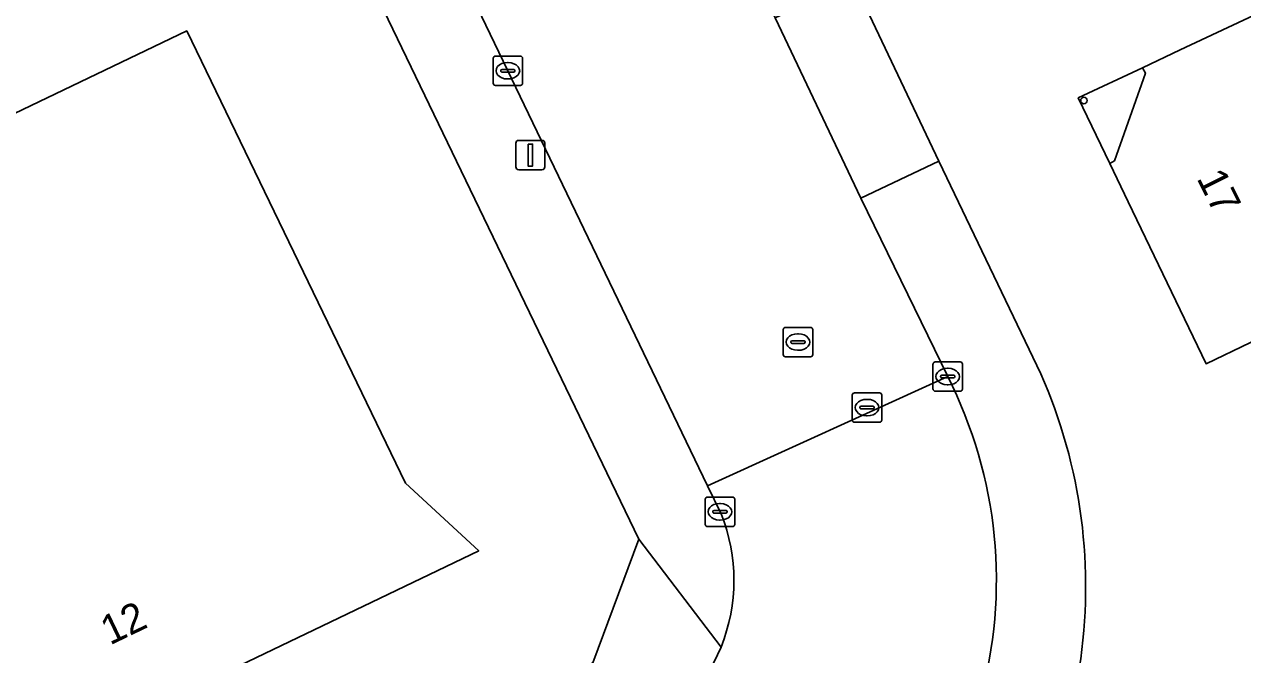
# Model space of a CAD drawing. Extents: x 157692 to 159674, y 381452 to 383291.
# Drawn here: x 158101.97 to 158143.43, y 381697.38 to 381718.82 of the extents above; entities that cross this region are included whole.
import ezdxf

# ---------------------------------------------------------------- set-up
doc = ezdxf.new("R2010")
doc.units = 0
for name, color, linetype in [('IMGEO_Erf', 7, 'Continuous'), ('IMGEO_Kolk', 7, 'Continuous'), ('IMGEO_Lichtmast', 7, 'Continuous'), ('IMGEO_Pand', 7, 'Continuous'), ('IMGEO_Pand_nummerreeks', 7, 'Continuous'), ('IMGEO_Pand_overbouw', 7, 'Continuous'), ('IMGEO_Rijbaan_lokaal_gesloten', 7, 'Continuous'), ('IMGEO_Rioolput', 7, 'Continuous'), ('IMGEO_Voetpad_open', 7, 'Continuous')]:
    doc.layers.add(name, color=color, linetype=linetype)

msp = doc.modelspace()

# ---------------------------------------------------------------- linework, layer by layer
at = {"layer": 'IMGEO_Erf'}
for points in [[(158092.487, 381798.744), (158092.916, 381798.939), (158095.512, 381792.931), (158095.193, 381792.79), (158096.925, 381789.189), (158099.538, 381783.755), (158104.632, 381773.16), (158105.509, 381771.337), (158108.516, 381765.1), (158109.23, 381763.603), (158112.225, 381757.328), (158115.269, 381751.09), (158115.795, 381750), (158119.248, 381742.84), (158125.511, 381729.855), (158128.564, 381723.514), (158130.19, 381720.284), (158133.095, 381714.162), (158136.569, 381706.935)], [(158006.881, 381609.083), (158005.905, 381627.867), (158005.466, 381636.382), (158005.223, 381641.106), (158032.78, 381654.365), (158038.282, 381657.004), (158060.573, 381667.757), (158067.21, 381670.951), (158069.612, 381672.132), (158075.377, 381674.875), (158095.213, 381684.451), (158107.373, 381690.341), (158121.318, 381697.1), (158122.884, 381701.311), (158109.399, 381729.267), (158106.88, 381734.578), (158102.545, 381743.606), (158102.331, 381744.049), (158099.751, 381749.471), (158099.496, 381750), (158086.302, 381777.417), (158083.311, 381783.632), (158080.659, 381789.142)]]:
    msp.add_lwpolyline(points, dxfattribs=at)
for points in [[(158151.951, 381730.299), (158166.876, 381737.497), (158174.051, 381722.618), (158146.716, 381709.452), (158142.191, 381707.273), (158139.542, 381712.78), (158138.914, 381714.086), (158139.078, 381714.178), (158140.124, 381717.153), (158140.027, 381717.345), (158141.314, 381717.95), (158150.29, 381722.166), (158147.447, 381728.127)], [(158107.496, 381718.594), (158114.941, 381703.211), (158117.435, 381700.917), (158095.837, 381690.555), (158087.076, 381708.818)]]:
    msp.add_lwpolyline(points, close=True, dxfattribs=at)
for centre, radius, start, end in [((158138.034, 381716.229), 0.11, 0, 180), ((158138.034, 381716.229), 0.11, 180, 0), ((158120.126, 381699.695), 17.966, 351.1206, 23.7643)]:
    msp.add_arc(centre, radius, start, end, dxfattribs=at)
at = {"layer": 'IMGEO_Kolk'}
for p, q in [((158118.001, 381717.74), (158118.853, 381717.74)), ((158117.926, 381716.814), (158117.926, 381717.666)), ((158118.414, 381717.52), (158118.439, 381717.52)), ((158118.927, 381717.666), (158118.927, 381716.814)), ((158118.185, 381717.234), (158118.185, 381717.246)), ((158118.623, 381717.197), (158118.225, 381717.197)), ((158118.228, 381717.283), (158118.626, 381717.283)), ((158118.437, 381716.96), (158118.412, 381716.96)), ((158118.669, 381717.246), (158118.669, 381717.234)), ((158118.853, 381716.74), (158118.001, 381716.74)), ((158132.971, 381707.34), (158133.823, 381707.34)), ((158132.896, 381706.414), (158132.896, 381707.266)), ((158133.384, 381707.12), (158133.409, 381707.12)), ((158133.897, 381707.266), (158133.897, 381706.414)), ((158133.155, 381706.834), (158133.155, 381706.846)), ((158133.593, 381706.797), (158133.195, 381706.797)), ((158133.198, 381706.883), (158133.596, 381706.883)), ((158133.407, 381706.56), (158133.382, 381706.56)), ((158133.639, 381706.846), (158133.639, 381706.834)), ((158133.823, 381706.34), (158132.971, 381706.34)), ((158125.146, 381701.813), (158125.146, 381702.665)), ((158125.221, 381702.739), (158126.073, 381702.739)), ((158125.634, 381702.519), (158125.659, 381702.519)), ((158126.147, 381702.665), (158126.147, 381701.813)), ((158125.405, 381702.233), (158125.405, 381702.245)), ((158125.843, 381702.196), (158125.445, 381702.196)), ((158125.448, 381702.282), (158125.846, 381702.282)), ((158125.657, 381701.959), (158125.632, 381701.959)), ((158125.889, 381702.245), (158125.889, 381702.233)), ((158126.073, 381701.739), (158125.221, 381701.739))]:
    msp.add_line(p, q, dxfattribs=at)
for points in [[(158118.001, 381717.74), (158118.853, 381717.74)], [(158117.926, 381716.814), (158117.926, 381717.666)], [(158118.927, 381717.666), (158118.927, 381716.814)], [(158118.853, 381716.74), (158118.001, 381716.74)], [(158132.971, 381707.34), (158133.823, 381707.34)], [(158132.896, 381706.414), (158132.896, 381707.266)], [(158133.897, 381707.266), (158133.897, 381706.414)], [(158133.823, 381706.34), (158132.971, 381706.34)], [(158125.146, 381701.813), (158125.146, 381702.665)], [(158125.221, 381702.739), (158126.073, 381702.739)], [(158126.147, 381702.665), (158126.147, 381701.813)], [(158126.073, 381701.739), (158125.221, 381701.739)]]:
    msp.add_lwpolyline(points, dxfattribs=at)
for centre, radius, start, end in [((158118.003, 381717.664), 0.0765, 91.552, 178.448), ((158118.003, 381717.664), 0.0765, 91.552, 178.448), ((158118.851, 381717.664), 0.0765, 1.552, 88.448), ((158118.851, 381717.664), 0.0765, 1.552, 88.448), ((158118.225, 381717.243), 0.0403, 85.8775, 175.7526), ((158118.222, 381717.233), 0.0366, 178.938, 274.7102), ((158118.626, 381717.24), 0.043, 264.8664, 352.4533), ((158118.63, 381717.245), 0.0386, 1.7309, 96.639), ((158118.003, 381716.816), 0.0765, 181.552, 268.448), ((158118.003, 381716.816), 0.0765, 181.552, 268.448), ((158118.851, 381716.816), 0.0765, 271.552, 358.448), ((158118.851, 381716.816), 0.0765, 271.552, 358.448), ((158132.973, 381707.264), 0.0765, 91.552, 178.448), ((158132.973, 381707.264), 0.0765, 91.552, 178.448), ((158133.821, 381707.264), 0.0765, 1.552, 88.448), ((158133.821, 381707.264), 0.0765, 1.552, 88.448), ((158133.195, 381706.843), 0.0403, 85.8775, 175.7526), ((158133.192, 381706.833), 0.0366, 178.938, 274.7102), ((158133.596, 381706.84), 0.043, 264.8664, 352.4533), ((158133.6, 381706.845), 0.0386, 1.7309, 96.639), ((158132.973, 381706.416), 0.0765, 181.552, 268.448), ((158132.973, 381706.416), 0.0765, 181.552, 268.448), ((158133.821, 381706.416), 0.0765, 271.552, 358.448), ((158133.821, 381706.416), 0.0765, 271.552, 358.448), ((158125.223, 381702.663), 0.0765, 91.552, 178.448), ((158125.223, 381702.663), 0.0765, 91.552, 178.448), ((158126.071, 381702.663), 0.0765, 1.552, 88.448), ((158126.071, 381702.663), 0.0765, 1.552, 88.448), ((158125.445, 381702.242), 0.0403, 85.8775, 175.7526), ((158125.442, 381702.232), 0.0366, 178.938, 274.7102), ((158125.846, 381702.239), 0.043, 264.8664, 352.4533), ((158125.85, 381702.244), 0.0386, 1.7309, 96.639), ((158125.223, 381701.815), 0.0765, 181.552, 268.448), ((158125.223, 381701.815), 0.0765, 181.552, 268.448), ((158126.071, 381701.815), 0.0765, 271.552, 358.448), ((158126.071, 381701.815), 0.0765, 271.552, 358.448)]:
    msp.add_arc(centre, radius, start, end, dxfattribs=at)
for centre, major_axis, ratio, start_param, end_param in [((158118.413, 381717.24), (-0.387, 0.002), 0.722429, 4.712389, 7.853982), ((158118.438, 381717.24), (-0.39, 0.002), 0.717154, 1.570796, 4.712389), ((158133.383, 381706.84), (-0.387, 0.002), 0.722429, 4.712389, 7.853982), ((158133.408, 381706.84), (-0.39, 0.002), 0.717154, 1.570796, 4.712389), ((158125.633, 381702.239), (-0.387, 0.002), 0.722429, 4.712389, 7.853982), ((158125.658, 381702.239), (-0.39, 0.002), 0.717154, 1.570796, 4.712389)]:
    msp.add_ellipse(centre, major_axis=major_axis, ratio=ratio, start_param=start_param, end_param=end_param, dxfattribs=at)
at = {"layer": 'IMGEO_Lichtmast'}
for p, q in [((158118.796, 381714.872), (158119.586, 381714.872)), ((158119.586, 381714.872), (158118.796, 381714.872)), ((158118.696, 381713.972), (158118.696, 381714.772)), ((158118.696, 381714.772), (158118.696, 381713.972)), ((158119.686, 381714.772), (158119.686, 381713.972)), ((158119.686, 381713.972), (158119.686, 381714.772)), ((158119.586, 381713.872), (158118.796, 381713.872)), ((158118.796, 381713.872), (158119.586, 381713.872))]:
    msp.add_line(p, q, dxfattribs=at)
msp.add_lwpolyline([(158119.116, 381714.747), (158119.266, 381714.747), (158119.266, 381713.997), (158119.116, 381713.997), (158119.116, 381714.747)], dxfattribs=at)
for centre, start, end in [((158118.796, 381714.772), 90, 180), ((158118.796, 381714.772), 90, 180), ((158119.586, 381714.772), 0, 90), ((158119.586, 381714.772), 360, 90), ((158118.796, 381713.972), 180, 270), ((158118.796, 381713.972), 180, 270), ((158119.586, 381713.972), 270, 0), ((158119.586, 381713.972), 270, 0)]:
    msp.add_arc(centre, 0.1, start, end, dxfattribs=at)
at = {"layer": 'IMGEO_Pand'}
for points in [[(158174.051, 381722.618), (158166.876, 381737.497), (158151.951, 381730.299), (158147.447, 381728.127), (158150.29, 381722.166), (158141.314, 381717.95), (158140.027, 381717.345), (158140.124, 381717.153), (158139.078, 381714.178), (158138.914, 381714.086), (158139.542, 381712.78), (158142.191, 381707.273), (158146.716, 381709.452)], [(158095.837, 381690.555), (158117.435, 381700.917), (158114.941, 381703.211), (158107.496, 381718.594), (158087.076, 381708.818)]]:
    msp.add_lwpolyline(points, close=True, dxfattribs=at)
for start, end in [(0, 180), (180, 0)]:
    msp.add_arc((158138.034, 381716.229), 0.11, start, end, dxfattribs=at)
at = {"layer": 'IMGEO_Pand_overbouw'}
msp.add_lwpolyline([(158138.914, 381714.086), (158139.078, 381714.178), (158140.124, 381717.153), (158140.027, 381717.345), (158137.84, 381716.318)], close=True, dxfattribs=at)
at = {"layer": 'IMGEO_Rijbaan_lokaal_gesloten'}
for points in [[(158102.661, 381750), (158104.936, 381745.273), (158109.491, 381735.808), (158112.026, 381730.541), (158125.222, 381703.122), (158133.396, 381706.839), (158130.435, 381712.908), (158127.521, 381719.041), (158125.912, 381722.3), (158122.883, 381728.587), (158116.624, 381741.577), (158112.648, 381749.831)], [(158133.396, 381706.839), (158125.222, 381703.122), (158125.682, 381702.167)]]:
    msp.add_lwpolyline(points, dxfattribs=at)
for centre, radius, start, end in [((158119.761, 381699.915), 15.292, 344.3737, 26.9211), ((158120.059, 381699.905), 6.061, 338.0595, 21.9151), ((158120.059, 381699.901), 6.06, 294.233, 338.0943)]:
    msp.add_arc(centre, radius, start, end, dxfattribs=at)
at = {"layer": 'IMGEO_Rioolput'}
for p, q in [((158127.801, 381707.586), (158127.801, 381708.438)), ((158127.876, 381708.512), (158128.728, 381708.512)), ((158128.289, 381708.292), (158128.314, 381708.292)), ((158128.802, 381708.438), (158128.802, 381707.586)), ((158128.06, 381708.006), (158128.06, 381708.018)), ((158128.498, 381707.969), (158128.1, 381707.969)), ((158128.103, 381708.055), (158128.501, 381708.055)), ((158128.544, 381708.018), (158128.544, 381708.006)), ((158128.728, 381707.512), (158127.876, 381707.512)), ((158128.312, 381707.732), (158128.287, 381707.732)), ((158130.15, 381705.358), (158130.15, 381706.21)), ((158130.225, 381706.284), (158131.077, 381706.284)), ((158131.151, 381706.21), (158131.151, 381705.358)), ((158130.409, 381705.778), (158130.409, 381705.79)), ((158130.847, 381705.741), (158130.449, 381705.741)), ((158130.452, 381705.827), (158130.85, 381705.827)), ((158130.638, 381706.064), (158130.663, 381706.064)), ((158130.893, 381705.79), (158130.893, 381705.778)), ((158131.077, 381705.284), (158130.225, 381705.284)), ((158130.661, 381705.504), (158130.636, 381705.504))]:
    msp.add_line(p, q, dxfattribs=at)
for points in [[(158127.801, 381707.586), (158127.801, 381708.438)], [(158127.876, 381708.512), (158128.728, 381708.512)], [(158128.802, 381708.438), (158128.802, 381707.586)], [(158128.728, 381707.512), (158127.876, 381707.512)], [(158130.15, 381705.358), (158130.15, 381706.21)], [(158130.225, 381706.284), (158131.077, 381706.284)], [(158131.151, 381706.21), (158131.151, 381705.358)], [(158131.077, 381705.284), (158130.225, 381705.284)]]:
    msp.add_lwpolyline(points, dxfattribs=at)
for centre, radius, start, end in [((158127.878, 381708.436), 0.0765, 91.552, 178.448), ((158127.878, 381708.436), 0.0765, 91.552, 178.448), ((158128.726, 381708.436), 0.0765, 1.552, 88.448), ((158128.726, 381708.436), 0.0765, 1.552, 88.448), ((158128.1, 381708.015), 0.0403, 85.8775, 175.7526), ((158128.097, 381708.005), 0.0366, 178.938, 274.7102), ((158128.501, 381708.012), 0.043, 264.8664, 352.4533), ((158128.505, 381708.017), 0.0386, 1.7309, 96.639), ((158127.878, 381707.588), 0.0765, 181.552, 268.448), ((158127.878, 381707.588), 0.0765, 181.552, 268.448), ((158128.726, 381707.588), 0.0765, 271.552, 358.448), ((158128.726, 381707.588), 0.0765, 271.552, 358.448), ((158130.227, 381706.208), 0.0765, 91.552, 178.448), ((158130.227, 381706.208), 0.0765, 91.552, 178.448), ((158131.075, 381706.208), 0.0765, 1.552, 88.448), ((158131.075, 381706.208), 0.0765, 1.552, 88.448), ((158130.449, 381705.787), 0.0403, 85.8775, 175.7526), ((158130.446, 381705.777), 0.0366, 178.938, 274.7102), ((158130.85, 381705.784), 0.043, 264.8664, 352.4533), ((158130.854, 381705.789), 0.0386, 1.7309, 96.639), ((158130.227, 381705.36), 0.0765, 181.552, 268.448), ((158130.227, 381705.36), 0.0765, 181.552, 268.448), ((158131.075, 381705.36), 0.0765, 271.552, 358.448), ((158131.075, 381705.36), 0.0765, 271.552, 358.448)]:
    msp.add_arc(centre, radius, start, end, dxfattribs=at)
for centre, major_axis, ratio, start_param, end_param in [((158128.288, 381708.012), (-0.387, 0.002), 0.722429, 4.712389, 7.853982), ((158128.313, 381708.012), (-0.39, 0.002), 0.717154, 1.570796, 4.712389), ((158130.637, 381705.784), (-0.387, 0.002), 0.722429, 4.712389, 7.853982), ((158130.662, 381705.784), (-0.39, 0.002), 0.717154, 1.570796, 4.712389)]:
    msp.add_ellipse(centre, major_axis=major_axis, ratio=ratio, start_param=start_param, end_param=end_param, dxfattribs=at)
at = {"layer": 'IMGEO_Voetpad_open'}
for points in [[(158112.026, 381730.541), (158109.399, 381729.267), (158122.884, 381701.311), (158125.681, 381697.64)], [(158125.682, 381702.167), (158125.222, 381703.122), (158112.026, 381730.541)], [(158136.569, 381706.935), (158133.095, 381714.162), (158130.435, 381712.908), (158133.396, 381706.839)], [(158125.681, 381697.64), (158122.884, 381701.311), (158121.318, 381697.1), (158107.373, 381690.341), (158095.213, 381684.451), (158075.377, 381674.875), (158076.639, 381672.23), (158120.418, 381693.339)]]:
    msp.add_lwpolyline(points, dxfattribs=at)
msp.add_lwpolyline([(158130.435, 381712.908), (158133.095, 381714.162), (158130.19, 381720.284), (158127.521, 381719.041)], close=True, dxfattribs=at)
for centre, radius, start, end in [((158120.126, 381699.695), 17.966, 351.1206, 23.7643), ((158119.761, 381699.915), 15.292, 344.3737, 26.9211), ((158120.059, 381699.905), 6.061, 338.0595, 21.9151), ((158120.059, 381699.901), 6.06, 294.233, 338.0943)]:
    msp.add_arc(centre, radius, start, end, dxfattribs=at)

# ---------------------------------------------------------------- texts
at = {"layer": 'IMGEO_Pand_nummerreeks'}
for s, rotation, p in [('17', 296.4993, (158141.859, 381713.587)), ('12', 25.6301, (158104.881, 381697.689))]:
    msp.add_text(s, height=1, rotation=rotation, dxfattribs=at).set_placement(p)

doc.saveas('drawing.dxf')
